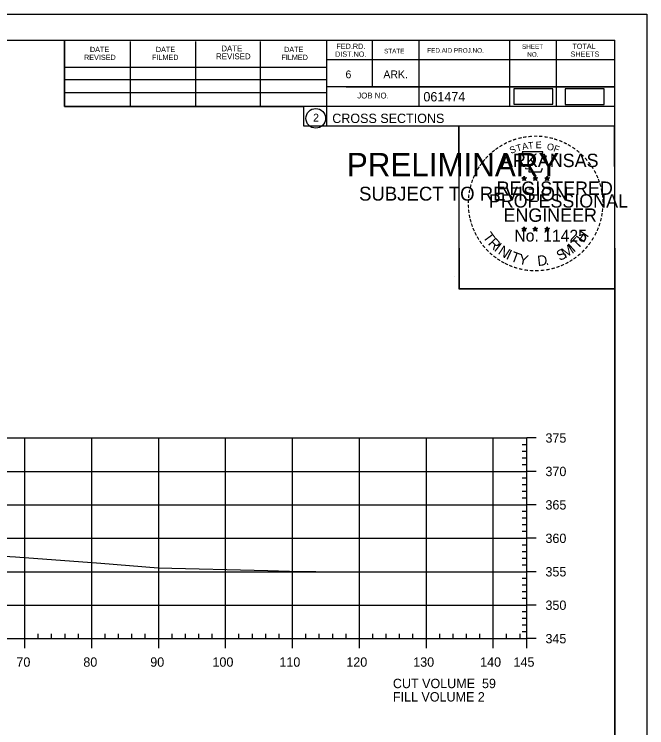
# Model space of a CAD drawing. Extents: x 1359801 to 1362404, y 372415 to 374228.
# Drawn here: x 1360039.8 to 1360134.3, y 373694.6 to 373801.3 of the extents above; entities that cross this region are included whole.
import ezdxf

# ---------------------------------------------------------------- set-up
doc = ezdxf.new("R2010")
doc.units = 0
for name, color, linetype in [('S_DRG_PT_SYM', 7, 'Continuous'), ('S_MAILBOX', 7, 'Continuous'), ('S_PRIMARY_CTL', 7, 'Continuous'), ('S_PRIMARY_CTL_ANNOT', 7, 'Continuous'), ('S_SHOULDER', 7, 'Continuous'), ('S_TELEPHONE_UTILITIES', 7, 'Continuous'), ('S_UNDERGROUND_CABLE', 7, 'Continuous'), ('S_UTL_PT_SYM', 7, 'Continuous'), ('S_WATER_UTILITIES', 7, 'Continuous')]:
    doc.layers.add(name, color=color, linetype=linetype)

msp = doc.modelspace()

# ---------------------------------------------------------------- linework, layer by layer
at = {"layer": 'S_DRG_PT_SYM'}
msp.add_lwpolyline([(1360024.66, 373721.07), (1360039.94, 373720.16), (1360052.68, 373719.21), (1360061.25, 373718.55), (1360077.68, 373718.12), (1360082.48, 373717.99), (1360084.81, 373718)], dxfattribs=at)
at = {"layer": 'S_MAILBOX'}
for p, q in [((1359826.35, 373737.94), (1360116.35, 373737.94)), ((1360041.35, 373707.94), (1360041.35, 373737.94)), ((1360051.35, 373707.94), (1360051.35, 373737.94)), ((1360061.35, 373707.94), (1360061.35, 373737.94)), ((1360071.35, 373707.94), (1360071.35, 373737.94)), ((1360081.35, 373707.94), (1360081.35, 373737.94)), ((1360091.35, 373707.94), (1360091.35, 373737.94)), ((1360101.35, 373707.94), (1360101.35, 373737.94)), ((1360111.35, 373707.94), (1360111.35, 373737.94)), ((1360116.35, 373707.94), (1360116.35, 373737.94)), ((1359826.35, 373732.94), (1360116.35, 373732.94)), ((1359826.35, 373727.94), (1360116.35, 373727.94)), ((1359826.35, 373722.94), (1360116.35, 373722.94)), ((1359826.35, 373717.94), (1360116.35, 373717.94)), ((1359826.35, 373712.94), (1360116.35, 373712.94)), ((1359826.35, 373707.94), (1360116.35, 373707.94))]:
    msp.add_line(p, q, dxfattribs=at)
at = {"layer": 'S_SHOULDER'}
for p, q in [((1359800.95, 373801.29), (1360134.28, 373801.29)), ((1360105.56, 373762.14), (1360105.56, 373762.14))]:
    msp.add_line(p, q, dxfattribs=at)
for points in [[(1359800.94, 373801.29), (1360134.28, 373801.29), (1360134.28, 373587.95), (1359800.94, 373587.95)], [(1360047.27, 373797.4), (1360047.27, 373787.52), (1360083, 373787.52), (1360083, 373784.6), (1360106.2, 373784.6), (1360106.2, 373760.26), (1360129.53, 373760.26), (1360129.53, 373591.94), (1359813.35, 373591.94), (1359813.35, 373797.4)], [(1360106.2, 373784.6), (1360129.41, 373784.6), (1360129.53, 373760.26), (1360106.32, 373760.26)]]:
    msp.add_lwpolyline(points, close=True, dxfattribs=at)
at = {"layer": 'S_TELEPHONE_UTILITIES'}
for p, q in [((1360115.96, 373777.1), (1360115.92, 373776.85)), ((1360115.96, 373776.74), (1360115.96, 373777.1)), ((1360115.96, 373777.1), (1360116.01, 373776.85)), ((1360117.63, 373777.1), (1360117.59, 373776.85)), ((1360117.63, 373776.74), (1360117.63, 373777.1)), ((1360117.63, 373777.1), (1360117.68, 373776.85)), ((1360119.4, 373777.09), (1360119.36, 373776.84)), ((1360119.4, 373776.73), (1360119.4, 373777.09)), ((1360119.4, 373777.09), (1360119.45, 373776.84)), ((1360115.62, 373776.85), (1360115.96, 373776.74)), ((1360115.62, 373776.85), (1360115.87, 373776.81)), ((1360115.62, 373776.85), (1360115.85, 373776.73)), ((1360115.75, 373776.44), (1360115.96, 373776.74)), ((1360115.75, 373776.44), (1360115.87, 373776.69)), ((1360115.75, 373776.44), (1360115.96, 373776.66)), ((1360116.31, 373776.85), (1360115.96, 373776.74)), ((1360116.18, 373776.44), (1360115.96, 373776.74)), ((1360116.18, 373776.44), (1360115.96, 373776.66)), ((1360116.31, 373776.85), (1360116.03, 373776.8)), ((1360116.18, 373776.44), (1360116.04, 373776.73)), ((1360116.31, 373776.85), (1360116.11, 373776.75)), ((1360117.29, 373776.85), (1360117.63, 373776.74)), ((1360117.29, 373776.85), (1360117.54, 373776.81)), ((1360117.29, 373776.85), (1360117.52, 373776.73)), ((1360117.42, 373776.44), (1360117.63, 373776.74)), ((1360117.42, 373776.44), (1360117.54, 373776.69)), ((1360117.42, 373776.44), (1360117.63, 373776.66)), ((1360117.98, 373776.85), (1360117.63, 373776.74)), ((1360117.85, 373776.44), (1360117.63, 373776.74)), ((1360117.85, 373776.44), (1360117.63, 373776.66)), ((1360117.98, 373776.85), (1360117.7, 373776.8)), ((1360117.85, 373776.44), (1360117.71, 373776.73)), ((1360117.98, 373776.85), (1360117.78, 373776.75)), ((1360119.05, 373776.84), (1360119.4, 373776.73)), ((1360119.05, 373776.84), (1360119.3, 373776.79)), ((1360119.05, 373776.84), (1360119.29, 373776.72)), ((1360119.18, 373776.43), (1360119.4, 373776.73)), ((1360119.18, 373776.43), (1360119.31, 373776.67)), ((1360119.18, 373776.43), (1360119.4, 373776.65)), ((1360119.75, 373776.84), (1360119.4, 373776.73)), ((1360119.61, 373776.43), (1360119.4, 373776.73)), ((1360119.61, 373776.43), (1360119.4, 373776.64)), ((1360119.75, 373776.84), (1360119.46, 373776.79)), ((1360119.61, 373776.43), (1360119.47, 373776.72)), ((1360119.75, 373776.84), (1360119.54, 373776.74)), ((1360115.61, 373769.28), (1360115.96, 373769.17)), ((1360115.61, 373769.28), (1360115.86, 373769.23)), ((1360115.61, 373769.28), (1360115.85, 373769.16)), ((1360115.74, 373768.87), (1360115.96, 373769.17)), ((1360115.74, 373768.87), (1360115.87, 373769.11)), ((1360115.74, 373768.87), (1360115.96, 373769.09)), ((1360115.96, 373769.53), (1360115.92, 373769.28)), ((1360115.96, 373769.17), (1360115.96, 373769.53)), ((1360115.96, 373769.53), (1360116.01, 373769.28)), ((1360116.31, 373769.28), (1360115.96, 373769.17)), ((1360116.17, 373768.87), (1360115.96, 373769.17)), ((1360116.17, 373768.87), (1360115.96, 373769.08)), ((1360116.31, 373769.28), (1360116.02, 373769.23)), ((1360116.17, 373768.87), (1360116.04, 373769.16)), ((1360116.31, 373769.28), (1360116.1, 373769.18)), ((1360117.28, 373769.28), (1360117.63, 373769.17)), ((1360117.28, 373769.28), (1360117.53, 373769.23)), ((1360117.28, 373769.28), (1360117.52, 373769.16)), ((1360117.41, 373768.87), (1360117.63, 373769.17)), ((1360117.41, 373768.87), (1360117.54, 373769.11)), ((1360117.41, 373768.87), (1360117.63, 373769.09)), ((1360117.63, 373769.53), (1360117.59, 373769.28)), ((1360117.63, 373769.17), (1360117.63, 373769.53)), ((1360117.63, 373769.53), (1360117.68, 373769.28)), ((1360117.98, 373769.28), (1360117.63, 373769.17)), ((1360117.84, 373768.87), (1360117.63, 373769.17)), ((1360117.84, 373768.87), (1360117.63, 373769.08)), ((1360117.98, 373769.28), (1360117.69, 373769.23)), ((1360117.84, 373768.87), (1360117.71, 373769.16)), ((1360117.98, 373769.28), (1360117.77, 373769.18)), ((1360119.05, 373769.27), (1360119.4, 373769.16)), ((1360119.05, 373769.27), (1360119.3, 373769.22)), ((1360119.05, 373769.27), (1360119.28, 373769.15)), ((1360119.18, 373768.86), (1360119.4, 373769.16)), ((1360119.18, 373768.86), (1360119.31, 373769.1)), ((1360119.18, 373768.86), (1360119.39, 373769.08)), ((1360119.4, 373769.52), (1360119.36, 373769.27)), ((1360119.61, 373768.86), (1360119.39, 373769.07)), ((1360119.4, 373769.16), (1360119.4, 373769.52)), ((1360119.4, 373769.52), (1360119.45, 373769.27)), ((1360119.74, 373769.27), (1360119.4, 373769.16)), ((1360119.61, 373768.86), (1360119.4, 373769.16)), ((1360119.74, 373769.27), (1360119.46, 373769.22)), ((1360119.61, 373768.86), (1360119.47, 373769.15)), ((1360119.74, 373769.27), (1360119.54, 373769.17))]:
    msp.add_line(p, q, dxfattribs=at)
for points in [[(1360115.66, 373780.73), (1360115.93, 373779.9)], [(1360119.17, 373779.81), (1360119.31, 373780.09), (1360118.62, 373780.07), (1360118.77, 373780.73), (1360115.66, 373780.73)], [(1360116.15, 373778.31), (1360116.15, 373778.22), (1360116.71, 373778.2), (1360116.66, 373777.73), (1360118.53, 373777.73), (1360118.73, 373778.26)], [(1360115.96, 373777.1), (1360116.18, 373776.44), (1360115.62, 373776.85), (1360116.31, 373776.85), (1360115.75, 373776.44), (1360115.96, 373777.1)], [(1360117.63, 373777.1), (1360117.85, 373776.44), (1360117.29, 373776.85), (1360117.98, 373776.85), (1360117.42, 373776.44), (1360117.63, 373777.1)], [(1360119.4, 373777.09), (1360119.61, 373776.43), (1360119.05, 373776.84), (1360119.75, 373776.84), (1360119.18, 373776.43), (1360119.4, 373777.09)], [(1360115.96, 373769.53), (1360116.17, 373768.87), (1360115.61, 373769.28), (1360116.31, 373769.28), (1360115.74, 373768.87), (1360115.96, 373769.53)], [(1360117.63, 373769.53), (1360117.84, 373768.87), (1360117.28, 373769.28), (1360117.98, 373769.28), (1360117.41, 373768.87), (1360117.63, 373769.53)], [(1360119.4, 373769.52), (1360119.61, 373768.86), (1360119.05, 373769.27), (1360119.74, 373769.27), (1360119.18, 373768.86), (1360119.4, 373769.52)]]:
    msp.add_lwpolyline(points, dxfattribs=at)
for centre, radius in [((1360115.96, 373776.74), 0.172), ((1360115.96, 373776.74), 0.145), ((1360115.96, 373776.74), 0.116), ((1360115.96, 373776.74), 0.0991), ((1360115.96, 373776.74), 0.0747), ((1360115.96, 373776.74), 0.0495), ((1360115.96, 373776.74), 0.0296), ((1360117.63, 373776.74), 0.172), ((1360117.63, 373776.74), 0.145), ((1360117.63, 373776.74), 0.116), ((1360117.63, 373776.74), 0.0991), ((1360117.63, 373776.74), 0.0747), ((1360117.63, 373776.74), 0.0495), ((1360117.63, 373776.74), 0.0296), ((1360119.4, 373776.73), 0.172), ((1360119.4, 373776.73), 0.145), ((1360119.4, 373776.73), 0.116), ((1360119.4, 373776.73), 0.0991), ((1360119.4, 373776.73), 0.0747), ((1360119.4, 373776.73), 0.0495), ((1360119.4, 373776.73), 0.0296), ((1360115.96, 373769.17), 0.172), ((1360115.96, 373769.17), 0.145), ((1360115.96, 373769.17), 0.116), ((1360115.96, 373769.17), 0.0991), ((1360115.96, 373769.17), 0.0747), ((1360115.96, 373769.17), 0.0495), ((1360115.96, 373769.17), 0.0296), ((1360117.63, 373769.17), 0.172), ((1360117.63, 373769.17), 0.145), ((1360117.63, 373769.17), 0.116), ((1360117.63, 373769.17), 0.0991), ((1360117.63, 373769.17), 0.0747), ((1360117.63, 373769.17), 0.0495), ((1360117.63, 373769.17), 0.0296), ((1360119.4, 373769.16), 0.172), ((1360119.4, 373769.16), 0.145), ((1360119.4, 373769.16), 0.116), ((1360119.4, 373769.16), 0.0991), ((1360119.4, 373769.16), 0.0747), ((1360119.4, 373769.16), 0.0495), ((1360119.4, 373769.16), 0.0296)]:
    msp.add_circle(centre, radius, dxfattribs=at)
at = {"layer": 'S_UNDERGROUND_CABLE'}
for points in [[(1360114.41, 373787.83), (1360120.25, 373787.83), (1360120.25, 373790.14), (1360114.41, 373790.14)], [(1360122.11, 373787.82), (1360127.94, 373787.82), (1360127.94, 373790.13), (1360122.11, 373790.13)]]:
    msp.add_lwpolyline(points, close=True, dxfattribs=at)
at = {"layer": 'S_UTL_PT_SYM'}
for p, q in [((1359813.35, 373797.4), (1360129.53, 373797.4)), ((1360047.27, 373787.52), (1360047.27, 373797.4)), ((1360086.43, 373797.4), (1360086.43, 373784.6)), ((1360093.27, 373797.4), (1360093.27, 373790.46)), ((1360100.21, 373797.4), (1360100.21, 373787.52)), ((1360113.79, 373797.4), (1360113.79, 373787.52)), ((1360120.73, 373797.4), (1360120.73, 373787.52)), ((1360129.53, 373591.94), (1360129.53, 373797.4)), ((1360057.13, 373787.52), (1360057.13, 373797.2)), ((1360066.89, 373787.52), (1360066.89, 373797.2)), ((1360076.57, 373787.52), (1360076.57, 373797.2)), ((1360129.53, 373794.46), (1360086.43, 373794.46)), ((1360129.53, 373794.48), (1360129.53, 373794.48)), ((1360047.27, 373793.38), (1360086.43, 373793.38)), ((1360047.27, 373791.52), (1360086.43, 373791.52)), ((1360129.53, 373790.46), (1360086.43, 373790.46)), ((1360089.39, 373790.46), (1360129.53, 373790.46)), ((1360047.27, 373787.52), (1360047.27, 373789.58)), ((1360047.27, 373789.58), (1360086.43, 373789.58)), ((1360129.53, 373787.52), (1360047.27, 373787.52)), ((1360086.43, 373784.6), (1360129.53, 373784.6))]:
    msp.add_line(p, q, dxfattribs=at)
msp.add_circle((1360084.82, 373785.73), 1.47, dxfattribs=at)
at = {"layer": 'S_WATER_UTILITIES'}
for p, q in [((1360116.35, 373707.94), (1360116.35, 373737.94)), ((1360117.75, 373737.94), (1360116.35, 373737.94)), ((1360116.35, 373736.94), (1360115.65, 373736.94)), ((1360116.35, 373735.94), (1360115.65, 373735.94)), ((1360116.35, 373734.94), (1360115.65, 373734.94)), ((1360116.35, 373733.94), (1360115.65, 373733.94)), ((1360117.75, 373732.94), (1360116.35, 373732.94)), ((1360116.35, 373731.94), (1360115.65, 373731.94)), ((1360116.35, 373730.94), (1360115.65, 373730.94)), ((1360116.35, 373729.94), (1360115.65, 373729.94)), ((1360116.35, 373728.94), (1360115.65, 373728.94)), ((1360117.75, 373727.94), (1360116.35, 373727.94)), ((1360116.35, 373726.94), (1360115.65, 373726.94)), ((1360116.35, 373725.94), (1360115.65, 373725.94)), ((1360116.35, 373724.94), (1360115.65, 373724.94)), ((1360116.35, 373723.94), (1360115.65, 373723.94)), ((1360117.75, 373722.94), (1360116.35, 373722.94)), ((1360116.35, 373721.94), (1360115.65, 373721.94)), ((1360116.35, 373720.94), (1360115.65, 373720.94)), ((1360116.35, 373719.94), (1360115.65, 373719.94)), ((1360116.35, 373718.94), (1360115.65, 373718.94)), ((1360117.75, 373717.94), (1360116.35, 373717.94)), ((1360116.35, 373716.94), (1360115.65, 373716.94)), ((1360116.35, 373715.94), (1360115.65, 373715.94)), ((1360116.35, 373714.94), (1360115.65, 373714.94)), ((1360116.35, 373713.94), (1360115.65, 373713.94)), ((1360117.75, 373712.94), (1360116.35, 373712.94)), ((1360116.35, 373711.94), (1360115.65, 373711.94)), ((1360116.35, 373710.94), (1360115.65, 373710.94)), ((1360116.35, 373709.94), (1360115.65, 373709.94)), ((1360116.35, 373708.94), (1360115.65, 373708.94)), ((1359826.35, 373707.94), (1360116.35, 373707.94)), ((1360041.35, 373706.54), (1360041.35, 373707.94)), ((1360043.35, 373707.94), (1360043.35, 373708.64)), ((1360045.35, 373707.94), (1360045.35, 373708.64)), ((1360047.35, 373707.94), (1360047.35, 373708.64)), ((1360049.35, 373707.94), (1360049.35, 373708.64)), ((1360051.35, 373706.54), (1360051.35, 373707.94)), ((1360053.35, 373707.94), (1360053.35, 373708.64)), ((1360055.35, 373707.94), (1360055.35, 373708.64)), ((1360057.35, 373707.94), (1360057.35, 373708.64)), ((1360059.35, 373707.94), (1360059.35, 373708.64)), ((1360061.35, 373706.54), (1360061.35, 373707.94)), ((1360063.35, 373707.94), (1360063.35, 373708.64)), ((1360065.35, 373707.94), (1360065.35, 373708.64)), ((1360067.35, 373707.94), (1360067.35, 373708.64)), ((1360069.35, 373707.94), (1360069.35, 373708.64)), ((1360071.35, 373706.54), (1360071.35, 373707.94)), ((1360073.35, 373707.94), (1360073.35, 373708.64)), ((1360075.35, 373707.94), (1360075.35, 373708.64)), ((1360077.35, 373707.94), (1360077.35, 373708.64)), ((1360079.35, 373707.94), (1360079.35, 373708.64)), ((1360081.35, 373706.54), (1360081.35, 373707.94)), ((1360083.35, 373707.94), (1360083.35, 373708.64)), ((1360085.35, 373707.94), (1360085.35, 373708.64)), ((1360087.35, 373707.94), (1360087.35, 373708.64)), ((1360089.35, 373707.94), (1360089.35, 373708.64)), ((1360091.35, 373706.54), (1360091.35, 373707.94)), ((1360093.35, 373707.94), (1360093.35, 373708.64)), ((1360095.35, 373707.94), (1360095.35, 373708.64)), ((1360097.35, 373707.94), (1360097.35, 373708.64)), ((1360099.35, 373707.94), (1360099.35, 373708.64)), ((1360101.35, 373706.54), (1360101.35, 373707.94)), ((1360103.35, 373707.94), (1360103.35, 373708.64)), ((1360105.35, 373707.94), (1360105.35, 373708.64)), ((1360107.35, 373707.94), (1360107.35, 373708.64)), ((1360109.35, 373707.94), (1360109.35, 373708.64)), ((1360111.35, 373706.54), (1360111.35, 373707.94)), ((1360113.35, 373707.94), (1360113.35, 373708.64)), ((1360115.35, 373707.94), (1360115.35, 373708.64)), ((1360116.35, 373706.54), (1360116.35, 373707.94)), ((1360117.75, 373707.94), (1360116.35, 373707.94))]:
    msp.add_line(p, q, dxfattribs=at)

# ---------------------------------------------------------------- texts
at = {"layer": 'S_PRIMARY_CTL'}
for s, p in [('375', (1360119.15, 373737.24)), ('370', (1360119.15, 373732.24)), ('365', (1360119.15, 373727.24)), ('360', (1360119.15, 373722.24)), ('355', (1360119.15, 373717.24)), ('350', (1360119.15, 373712.24)), ('345', (1360119.15, 373707.24)), ('70', (1360040.09, 373703.74)), ('80', (1360050.09, 373703.74)), ('90', (1360060.09, 373703.74)), ('100', (1360069.39, 373703.74)), ('110', (1360079.39, 373703.74)), ('120', (1360089.39, 373703.74)), ('130', (1360099.39, 373703.74)), ('140', (1360109.39, 373703.74)), ('145', (1360114.38, 373703.74)), ('CUT VOLUME  59', (1360096.35, 373700.54)), ('FILL VOLUME 2', (1360096.35, 373698.54))]:
    msp.add_text(s, height=1.4, dxfattribs=at).set_placement(p)
at = {"layer": 'S_PRIMARY_CTL_ANNOT'}
for s, height, p in [('PRELIMINARY', 3.5, (1360089.48, 373777.06)), ('DWB', 0.01, (1360090.23, 373778.91)), ('SUBJECT TO REVISION', 2.0751, (1360091.29, 373773.43))]:
    msp.add_text(s, height=height, rotation=360, dxfattribs=at).set_placement(p)
at = {"layer": 'S_TELEPHONE_UTILITIES'}
for s, height, rotation, p in [('-', 1.6, 24.3072, (1360113.77, 373781.59)), ('-', 1.6, 19.1761, (1360114.4, 373781.86)), ('-', 1.6, 13.6301, (1360115.15, 373782.1)), ('-', 1.6, 10.2193, (1360115.83, 373782.26)), ('-', 1.6, 5.8968, (1360116.56, 373782.37)), ('-', 1.6, 0.1862, (1360117.33, 373782.44)), ('-', 1.6, 357.743, (1360118.06, 373782.43)), ('-', 1.6, 352.1617, (1360118.8, 373782.37)), ('-', 1.6, 347.2049, (1360119.52, 373782.26)), ('-', 1.6, 342.3362, (1360120.15, 373782.1)), ('-', 1.6, 337.8551, (1360120.89, 373781.88)), ('-', 1.6, 36.2317, (1360111.96, 373780.5)), ('-', 1.6, 34.0636, (1360112.54, 373780.9)), ('-', 1.6, 28.7918, (1360113.14, 373781.27)), ('S', 1, 21.594, (1360114.01, 373780.41)), ('T', 1, 16.4036, (1360114.92, 373780.74)), ('A', 1, 11.2132, (1360115.75, 373780.99)), ('T', 1, 6.0228, (1360116.6, 373781.15)), ('E', 1, 0.8323, (1360117.7, 373781.26)), ('O', 1, 350.4515, (1360119.31, 373781.05)), ('F', 1, 340.0707, (1360120.26, 373780.83)), ('-', 1.6, 334.1211, (1360121.52, 373781.61)), ('-', 1.6, 329.6409, (1360122.1, 373781.33)), ('-', 1.6, 325.8627, (1360122.74, 373780.96)), ('-', 1.6, 42.9622, (1360111.05, 373779.71)), ('-', 1.6, 38.9507, (1360111.49, 373780.13)), ('ARKANSAS', 2, 360, (1360112.51, 373778.44)), ('-', 1.6, 320.5297, (1360123.35, 373780.54)), ('-', 1.6, 315.5786, (1360123.95, 373780.05)), ('-', 1.6, 50.6142, (1360110.2, 373778.75)), ('-', 1.6, 48.423, (1360110.6, 373779.23)), ('-', 1.6, 309.8797, (1360124.52, 373779.5)), ('-', 1.6, 306.6522, (1360125.04, 373778.9)), ('-', 1.6, 58.0706, (1360109.46, 373777.65)), ('-', 1.6, 54.2325, (1360109.79, 373778.18)), ('-', 1.4, 303.6753, (1360125.53, 373778.33)), ('-', 1.6, 67.7743, (1360108.89, 373776.43)), ('-', 1.6, 62.8713, (1360109.15, 373777.04)), ('-', 1.6, 299.6684, (1360125.85, 373777.72)), ('-', 1.6, 294.6628, (1360126.17, 373777.11)), ('-', 1.6, 72.3945, (1360108.67, 373775.8)), ('REGISTERED', 2, 360, (1360111.83, 373774.29)), ('DWB', 0.01, 360, (1360115.95, 373776.73)), ('DWB', 0.01, 360, (1360117.62, 373776.73)), ('DWB', 0.01, 360, (1360119.39, 373776.72)), ('-', 1.6, 290.5728, (1360126.43, 373776.53)), ('-', 1.6, 285.1233, (1360126.66, 373775.95)), ('-', 1.6, 81.2013, (1360108.34, 373774.37)), ('-', 1.6, 75.461, (1360108.48, 373775.08)), ('-', 1.6, 280.5493, (1360126.86, 373775.21)), ('-', 1.6, 85.1863, (1360108.27, 373773.68)), ('PROFESSIONAL', 2, 360, (1360110.68, 373772.39)), ('-', 1.6, 276.5962, (1360127.03, 373774.44)), ('-', 1.6, 94.1959, (1360108.28, 373772.25)), ('-', 1.6, 89.0622, (1360108.24, 373772.98)), ('-', 1.6, 274.3301, (1360127.09, 373773.72)), ('-', 1.6, 269.9407, (1360127.12, 373773.09)), ('-', 1.6, 98.9479, (1360108.35, 373771.59)), ('ENGINEER', 2, 360, (1360112.87, 373770.26)), ('-', 1.6, 263.5172, (1360127.1, 373772.42)), ('-', 1.6, 101.7149, (1360108.48, 373770.85)), ('-', 1.6, 105.4578, (1360108.65, 373770.26)), ('-', 1.6, 255.7626, (1360126.92, 373771.09)), ('-', 1.6, 260.9953, (1360127.03, 373771.77)), ('-', 1.6, 109.0874, (1360108.86, 373769.63)), ('-', 1.6, 252.8681, (1360126.74, 373770.37)), ('-', 1.6, 114.0643, (1360109.12, 373769.03)), ('-', 1.6, 115.7289, (1360109.42, 373768.41)), ('T', 1.54, 306.0406, (1360109.72, 373768.01)), ('No. 11425', 1.757, 360, (1360114.5, 373767.31)), ('DWB', 0.01, 360, (1360115.95, 373769.16)), ('DWB', 0.01, 360, (1360117.62, 373769.16)), ('DWB', 0.01, 360, (1360119.38, 373769.15)), ('H', 1.54, 54.6088, (1360124.84, 373767.04)), ('-', 1.6, 244.6197, (1360126.25, 373769.07)), ('-', 1.6, 247.8887, (1360126.52, 373769.7)), ('-', 1.6, 120.4471, (1360109.78, 373767.83)), ('R', 1.54, 314.005, (1360110.48, 373766.96)), ('T', 1.54, 46.6444, (1360123.95, 373766.1)), ('-', 1.6, 239.0712, (1360125.86, 373768.32)), ('-', 1.6, 125.8934, (1360110.18, 373767.27)), ('-', 1.6, 130.7181, (1360110.64, 373766.71)), ('I', 1.54, 321.9694, (1360111.38, 373766.03)), ('N', 1.54, 326.5002, (1360111.95, 373765.55)), ('M', 1.54, 32.6563, (1360122.1, 373764.77)), ('I', 1.54, 42.1136, (1360123.39, 373765.62)), ('-', 1.6, 231.2538, (1360125.03, 373767.1)), ('-', 1.6, 233.8452, (1360125.46, 373767.67)), ('-', 1.6, 134.2238, (1360111.16, 373766.17)), ('-', 1.6, 138.9338, (1360111.68, 373765.7)), ('I', 1.54, 335.3603, (1360113.16, 373764.77)), ('T', 1.54, 339.8912, (1360113.82, 373764.44)), ('Y', 1.54, 347.8556, (1360115.04, 373763.99)), ('S', 1.54, 26.9312, (1360121.27, 373764.37)), ('-', 1.6, 221.0851, (1360124.03, 373766.03)), ('-', 1.6, 225.7653, (1360124.55, 373766.54)), ('-', 1.6, 144.6463, (1360112.24, 373765.3)), ('-', 1.6, 148.0898, (1360112.8, 373764.93)), ('-', 1.6, 151.5704, (1360113.38, 373764.6)), ('D', 1.54, 6.3969, (1360118.02, 373763.64)), ('-', 1.6, 207.3568, (1360122.39, 373764.82)), ('-', 1.6, 212.2491, (1360122.94, 373765.17)), ('-', 1.6, 215.7363, (1360123.48, 373765.55)), ('-', 1.6, 154.6002, (1360113.9, 373764.36)), ('-', 1.6, 158.5612, (1360114.53, 373764.1)), ('-', 1.6, 162.7983, (1360115.21, 373763.89)), ('-', 1.6, 167.5555, (1360115.93, 373763.72)), ('-', 1.6, 191.2858, (1360119.74, 373763.79)), ('.', 1.54, 13.7642, (1360119.21, 373763.76)), ('-', 1.6, 195.4743, (1360120.47, 373763.99)), ('-', 1.6, 200.7184, (1360121.14, 373764.23)), ('-', 1.6, 204.2516, (1360121.76, 373764.5)), ('-', 1.6, 173.1155, (1360116.7, 373763.61)), ('-', 1.6, 176.5183, (1360117.45, 373763.56)), ('-', 1.6, 181.5918, (1360118.19, 373763.58)), ('-', 1.6, 185.8167, (1360119, 373763.66))]:
    msp.add_text(s, height=height, rotation=rotation, dxfattribs=at).set_placement(p)
at = {"layer": 'S_UTL_PT_SYM'}
for s, height, p in [('DATE', 0.782, (1360051.07, 373795.64)), ('DATE', 0.782, (1360060.93, 373795.64)), ('DATE', 0.879, (1360070.71, 373795.74)), ('DATE', 0.782, (1360080.09, 373795.64)), ('FED.RD.', 0.782, (1360087.91, 373796.12)), ('SHEET', 0.684, (1360115.65, 373796.12)), ('TOTAL', 0.782, (1360123.17, 373796.12)), ('REVISED', 0.782, (1360050.19, 373794.46)), ('FILMED', 0.782, (1360060.35, 373794.46)), ('REVISED', 0.879, (1360069.93, 373794.56)), ('FILMED', 0.782, (1360079.69, 373794.46)), ('DIST.NO.', 0.782, (1360087.71, 373794.94)), ('STATE', 0.684, (1360095.03, 373795.44)), ('FED.AID PROJ.NO.', 0.684, (1360101.49, 373795.54)), ('NO.', 0.684, (1360116.43, 373794.94)), ('SHEETS', 0.782, (1360122.89, 373794.94)), ('6', 1.17, (1360089.27, 373791.72)), ('ARK.', 1.172, (1360094.93, 373791.72)), ('JOB NO.', 0.879, (1360091.03, 373788.7)), ('061474', 1.4, (1360100.91, 373788.26)), ('2', 1.17, (1360084.43, 373785.25)), ('CROSS SECTIONS', 1.4, (1360087.29, 373785.03))]:
    msp.add_text(s, height=height, rotation=360, dxfattribs=at).set_placement(p)

doc.saveas('drawing.dxf')
